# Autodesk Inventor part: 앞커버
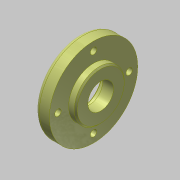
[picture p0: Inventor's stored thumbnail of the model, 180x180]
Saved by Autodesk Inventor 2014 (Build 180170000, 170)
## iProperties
Created: 2015-12
Part Number: 앞커버
Document SubType Name: Modeling
Designer: mdu
Density: 2.71 g/cm^3
Material: 알루미늄 6061
Mass: 70.9292 g
Surface Area: 93.9296 cm^2
Volume: 26.1731 cm^3
Appearance: 널링 45
Author: mdu
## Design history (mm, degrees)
sketch "스케치1"
  geometry: L1 (-7.5, 0)-(7.5, 0); L2 (-7.5, 0)-(-7.5, 31); L3 (-7.5, 31)-(2.5, 31); L4 (2.5, 31)-(2.5, 17.5); L5 (2.5, 17.5)-(7.5, 17.5); L6 (7.5, 17.5)-(7.5, 0); 2 further points
  constraints: 12 end point, 3 perpendicular, 1 coincident, 1 horizontal, 1 midpoint, 1 parallel
  dimensions: "d0" = 15 distance of L1.start L1.end; "d1" = 62 diameter of L3 L1; "d2" = 35 diameter of L5 L1; "d5" = 10 distance of L2.end L3.end
revolve "회전1" sketch "스케치1" stored, may be unused: angle "d6" = 90 deg
sketch "스케치2" dims "d42" = 50
  geometry: 3 further points
  constraints: 2 vertical alignment, 1 coincident, 2 other
hole "구멍1" sketch "스케치2" at (0, 25) diameter "d8" = 4.5; stored, may be unused: countersink angle "d12" = 90 deg, drill point angle "d14" = 118 deg; dims "d9" = 6, "d10" = 8, "d11" = 4.4, "d13" = 8
hole "구멍2" diameter "d20" = 18; stored, may be unused: countersink angle "d24" = 90 deg, drill point angle "d26" = 0 deg; dims "d18" = 10, "d19" = 10, "d21" = 6, "d22" = 8, "d23" = 4.4, "d25" = 8
hole "구멍3" diameter "d34" = 30; stored, may be unused: countersink angle "d38" = 90 deg, drill point angle "d40" = 0 deg; dims "d32" = 10, "d33" = 10, "d35" = 6, "d36" = 4, "d37" = 2, "d39" = 7.3
fillet "모깎기1" dims "d27" = 3, "d41" = 0.3
chamfer "모따기1" distance "d29" = 1; stored, may be unused: second distance "d30" = 2, angle "d31" = 45 deg
node "솔리드1"
pattern_circular "원형 패턴1" dims angle "d16" = 360 deg
